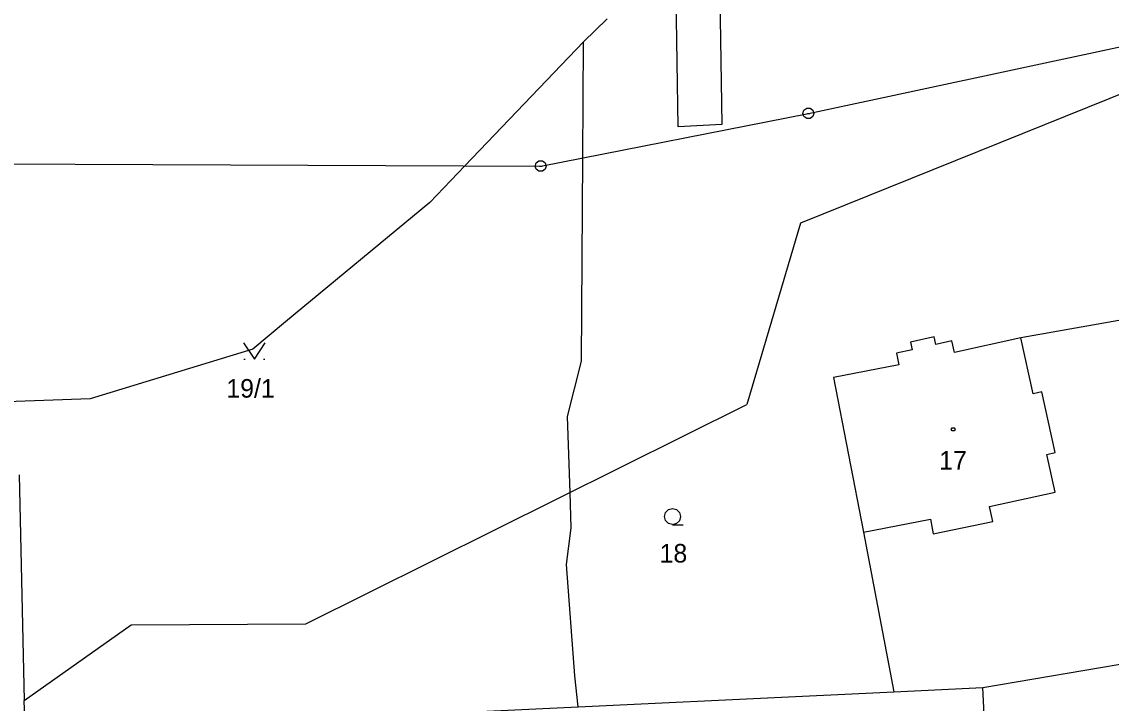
# Model space of a CAD drawing. Extents: x -759060 to -757386, y -1172273 to -1170948.
# Drawn here: x -757796.3 to -757696.5, y -1171236.4 to -1171174 of the extents above; entities that cross this region are included whole.
import ezdxf

# ---------------------------------------------------------------- set-up
doc = ezdxf.new("R2010")
doc.units = 0
for name, color, linetype in [('Vrstva 1', 7, 'Continuous'), ('Vrstva 11', 7, 'Continuous'), ('Vrstva 12', 7, 'Continuous'), ('Vrstva 13', 7, 'Continuous'), ('Vrstva 2', 7, 'Continuous'), ('Vrstva 3', 7, 'Continuous'), ('Vrstva 4', 7, 'Continuous'), ('Vrstva 5', 7, 'Continuous'), ('Vrstva 8', 7, 'Continuous')]:
    doc.layers.add(name, color=color, linetype=linetype)

msp = doc.modelspace()

# ---------------------------------------------------------------- linework, layer by layer
at = {"layer": 'Vrstva 1'}
for p, q in [((-757724.26, -1171182.42), (-757695.6, -1171176.3)), ((-757694.62, -1171180.23), (-757724.98, -1171192.45)), ((-757748.77, -1171187.25), (-757724.26, -1171182.42)), ((-757812.24, -1171186.95), (-757748.77, -1171187.25)), ((-757724.98, -1171192.45), (-757729.91, -1171209.06)), ((-757689.6, -1171200.27), (-757704.81, -1171202.96)), ((-757712.76, -1171202.86), (-757714.92, -1171203.34)), ((-757712.61, -1171203.56), (-757712.76, -1171202.86)), ((-757711.12, -1171203.23), (-757712.61, -1171203.56)), ((-757710.88, -1171204.31), (-757711.12, -1171203.23)), ((-757704.81, -1171202.96), (-757710.88, -1171204.31)), ((-757714.76, -1171204.04), (-757716.19, -1171204.36)), ((-757714.92, -1171203.34), (-757714.76, -1171204.04)), ((-757716.19, -1171204.36), (-757715.98, -1171205.42)), ((-757715.98, -1171205.42), (-757721.98, -1171206.59)), ((-757721.98, -1171206.59), (-757719.21, -1171220.75)), ((-757770.27, -1171229.12), (-757729.91, -1171209.06)), ((-757796.51, -1171215.5), (-757796.05, -1171236.15)), ((-757719.21, -1171220.75), (-757716.43, -1171235.34)), ((-757786.28, -1171229.21), (-757770.27, -1171229.12)), ((-757796.05, -1171236.15), (-757786.28, -1171229.21)), ((-757708.3, -1171234.95), (-757679.63, -1171230.08)), ((-757716.43, -1171235.34), (-757708.3, -1171234.95)), ((-757707.63, -1171247.69), (-757708.3, -1171234.95)), ((-757795.96, -1171239.11), (-757796.05, -1171236.15)), ((-757753.7, -1171237.12), (-757716.43, -1171235.34))]:
    msp.add_line(p, q, dxfattribs=at)
at = {"layer": 'Vrstva 11'}
for p, q in [((-757744.84, -1171175.87), (-757742.7, -1171173.77)), ((-757744.84, -1171175.87), (-757755.71, -1171187.22)), ((-757744.91, -1171186.49), (-757744.84, -1171175.87)), ((-757755.71, -1171187.22), (-757758.93, -1171190.58)), ((-757745.03, -1171205.09), (-757744.91, -1171186.49)), ((-757758.93, -1171190.58), (-757772.15, -1171201.48)), ((-757772.15, -1171201.48), (-757775.13, -1171204)), ((-757775.13, -1171204), (-757790.01, -1171208.53)), ((-757746.33, -1171210.16), (-757745.03, -1171205.09)), ((-757790.01, -1171208.53), (-757799.77, -1171208.88)), ((-757746.09, -1171217.1), (-757746.33, -1171210.16)), ((-757745.98, -1171220.33), (-757746.09, -1171217.1)), ((-757746.42, -1171223.71), (-757745.98, -1171220.33)), ((-757745.64, -1171233.88), (-757746.42, -1171223.71)), ((-757745.34, -1171236.72), (-757745.64, -1171233.88))]:
    msp.add_line(p, q, dxfattribs=at)
at = {"layer": 'Vrstva 12'}
for p, q in [((-757712.76, -1171202.86), (-757714.92, -1171203.34)), ((-757712.61, -1171203.56), (-757712.76, -1171202.86)), ((-757711.12, -1171203.23), (-757712.61, -1171203.56)), ((-757710.88, -1171204.31), (-757711.12, -1171203.23)), ((-757704.81, -1171202.96), (-757710.88, -1171204.31)), ((-757703.68, -1171208.07), (-757704.81, -1171202.96)), ((-757714.76, -1171204.04), (-757716.19, -1171204.36)), ((-757714.92, -1171203.34), (-757714.76, -1171204.04)), ((-757716.19, -1171204.36), (-757715.98, -1171205.42)), ((-757715.98, -1171205.42), (-757721.98, -1171206.59)), ((-757721.98, -1171206.59), (-757719.21, -1171220.75)), ((-757702.89, -1171207.9), (-757703.68, -1171208.07)), ((-757701.68, -1171213.46), (-757702.89, -1171207.9)), ((-757702.44, -1171213.63), (-757701.68, -1171213.46)), ((-757701.68, -1171217.07), (-757702.44, -1171213.63)), ((-757707.69, -1171218.4), (-757701.68, -1171217.07)), ((-757707.39, -1171219.75), (-757707.69, -1171218.4)), ((-757719.21, -1171220.75), (-757713.1, -1171219.55)), ((-757713.1, -1171219.55), (-757712.84, -1171220.88)), ((-757712.84, -1171220.88), (-757707.39, -1171219.75))]:
    msp.add_line(p, q, dxfattribs=at)
at = {"layer": 'Vrstva 13'}
for p, q in [((-757736.18, -1171183.64), (-757736.43, -1171167.03)), ((-757732.41, -1171168.65), (-757732.18, -1171183.44)), ((-757732.18, -1171183.44), (-757736.18, -1171183.64))]:
    msp.add_line(p, q, dxfattribs=at)
at = {"layer": 'Vrstva 3'}
for p, q in [((-757775.94, -1171204.92), (-757775.84, -1171204.92)), ((-757774.14, -1171204.92), (-757774.04, -1171204.92))]:
    msp.add_line(p, q, dxfattribs=at)
for points in [[(-757775.99, -1171203.42), (-757774.99, -1171204.92), (-757773.99, -1171203.42)], [(-757736.7, -1171220.04), (-757737.08, -1171219.94), (-757737.35, -1171219.67), (-757737.45, -1171219.3), (-757737.35, -1171218.93), (-757737.08, -1171218.66), (-757736.71, -1171218.56), (-757736.34, -1171218.66), (-757736.07, -1171218.93), (-757735.97, -1171219.31), (-757736.07, -1171219.69), (-757736.34, -1171219.96), (-757736.72, -1171220.06), (-757735.72, -1171220.06)]]:
    msp.add_lwpolyline(points, dxfattribs=at)
at = {"layer": 'Vrstva 4'}
for p, q in [((-757703.68, -1171208.07), (-757704.81, -1171202.96)), ((-757702.89, -1171207.9), (-757703.68, -1171208.07)), ((-757701.68, -1171213.46), (-757702.89, -1171207.9)), ((-757702.44, -1171213.63), (-757701.68, -1171213.46)), ((-757701.68, -1171217.07), (-757702.44, -1171213.63)), ((-757707.69, -1171218.4), (-757701.68, -1171217.07)), ((-757707.39, -1171219.75), (-757707.69, -1171218.4)), ((-757719.21, -1171220.75), (-757713.1, -1171219.55)), ((-757713.1, -1171219.55), (-757712.84, -1171220.88)), ((-757712.84, -1171220.88), (-757707.39, -1171219.75))]:
    msp.add_line(p, q, dxfattribs=at)
at = {"layer": 'Vrstva 5'}
msp.add_lwpolyline([(-757710.93, -1171211.18), (-757710.84, -1171211.33), (-757710.93, -1171211.48), (-757711.11, -1171211.48), (-757711.2, -1171211.33), (-757711.11, -1171211.18)], close=True, dxfattribs=at)
at = {"layer": 'Vrstva 8'}
for p, q in [((-757724.38, -1171182.42), (-757724.14, -1171182.42)), ((-757748.89, -1171187.25), (-757748.65, -1171187.25))]:
    msp.add_line(p, q, dxfattribs=at)
for points in [[(-757724.11, -1171181.94), (-757723.86, -1171182.12), (-757723.76, -1171182.41), (-757723.86, -1171182.7), (-757724.11, -1171182.88), (-757724.42, -1171182.88), (-757724.67, -1171182.7), (-757724.77, -1171182.41), (-757724.67, -1171182.12), (-757724.42, -1171181.94)], [(-757748.62, -1171186.77), (-757748.37, -1171186.95), (-757748.27, -1171187.24), (-757748.37, -1171187.53), (-757748.62, -1171187.71), (-757748.93, -1171187.71), (-757749.18, -1171187.53), (-757749.28, -1171187.24), (-757749.18, -1171186.95), (-757748.93, -1171186.77)]]:
    msp.add_lwpolyline(points, close=True, dxfattribs=at)

# ---------------------------------------------------------------- texts
at = {"layer": 'Vrstva 2'}
for s, p in [('19/1', (-757777.548, -1171208.43)), ('17', (-757712.287, -1171215.01)), ('18', (-757737.887, -1171223.52))]:
    msp.add_text(s, height=1.7, dxfattribs=at).set_placement(p)

doc.saveas('drawing.dxf')
